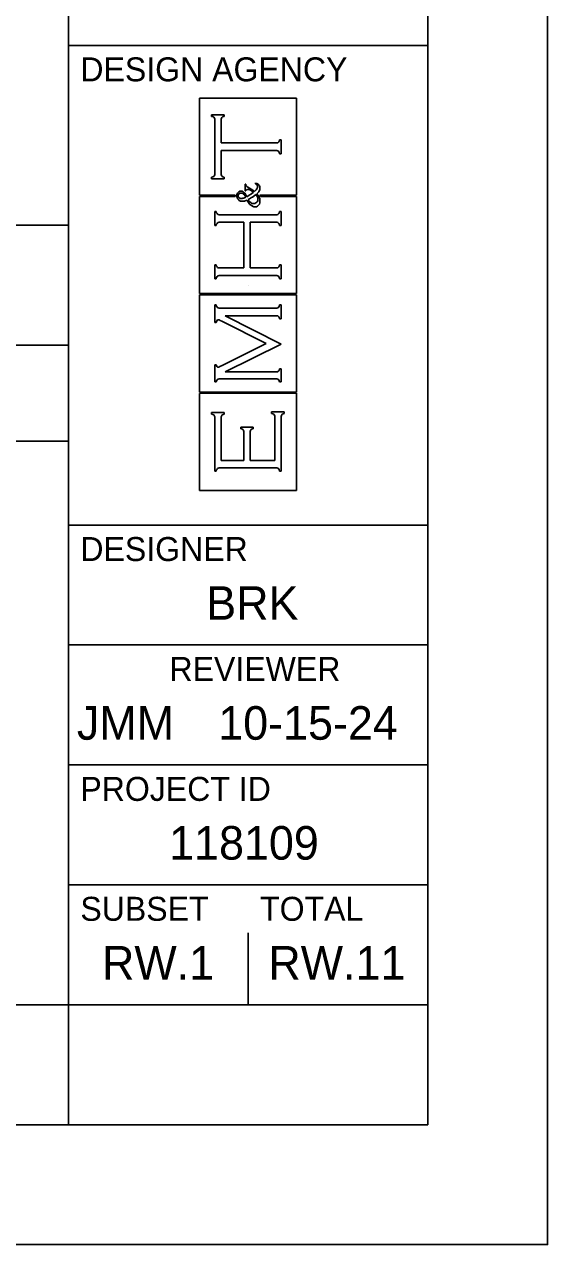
# Model space of a CAD drawing. Extents: x 0 to 34, y -5.4 to 22.
# Drawn here: x 31.82 to 34, y 0 to 5.09 of the extents above; entities that cross this region are included whole.
import ezdxf

# ---------------------------------------------------------------- set-up
doc = ezdxf.new("R2010")
doc.units = 0
for name, color, linetype in [('SH_Border', 7, 'Continuous'), ('SH_Cut_Line', 7, 'Continuous'), ('SH_Data', 7, 'Continuous')]:
    doc.layers.add(name, color=color, linetype=linetype)

msp = doc.modelspace()

# ---------------------------------------------------------------- linework, layer by layer
at = {"layer": 'SH_Border'}
for p, q in [((32, 0.5), (32, 21.5)), ((32, 5), (33.5, 5)), ((32, 3), (33.5, 3)), ((32, 2.5), (33.5, 2.5)), ((32, 2), (33.5, 2)), ((32, 1.5), (33.5, 1.5)), ((32, 1), (33.5, 1))]:
    msp.add_line(p, q, dxfattribs=at)
msp.add_lwpolyline([(1.5, 21.5), (33.5, 21.5), (33.5, 0.5), (1.5, 0.5)], close=True, dxfattribs=at)
at = {"layer": 'SH_Cut_Line'}
msp.add_lwpolyline([(0, 0), (34, 0), (34, 22), (0, 22)], close=True, dxfattribs=at)
at = {"layer": 'SH_Data'}
for p, q in [((32, 3.75), (32, 7)), ((32.9517, 4.7794), (32.547, 4.7794)), ((32.547, 4.7794), (32.547, 4.3748)), ((32.9517, 4.3748), (32.9517, 4.7794)), ((32.5978, 4.7041), (32.5978, 4.7106)), ((32.5978, 4.7106), (32.6505, 4.7106)), ((32.603, 4.7029), (32.5978, 4.7041)), ((32.6064, 4.7011), (32.603, 4.7029)), ((32.6082, 4.6987), (32.6064, 4.7011)), ((32.6099, 4.6964), (32.6082, 4.6987)), ((32.6108, 4.6924), (32.6099, 4.6964)), ((32.6108, 4.6867), (32.6108, 4.6924)), ((32.6108, 4.4675), (32.6108, 4.6867)), ((32.6383, 4.6964), (32.6375, 4.6924)), ((32.6375, 4.6924), (32.6375, 4.6867)), ((32.6375, 4.6867), (32.6375, 4.593)), ((32.64, 4.6987), (32.6383, 4.6964)), ((32.6418, 4.7011), (32.64, 4.6987)), ((32.6452, 4.7029), (32.6418, 4.7011)), ((32.6505, 4.7041), (32.6452, 4.7029)), ((32.6505, 4.7106), (32.6505, 4.7041)), ((32.6375, 4.593), (32.8639, 4.593)), ((32.8639, 4.593), (32.8695, 4.593)), ((32.8695, 4.593), (32.8734, 4.5939)), ((32.8734, 4.5939), (32.8758, 4.5956)), ((32.8758, 4.5956), (32.8782, 4.5974)), ((32.8782, 4.5974), (32.88, 4.6008)), ((32.88, 4.6008), (32.8814, 4.606)), ((32.8814, 4.606), (32.8879, 4.606)), ((32.8879, 4.606), (32.8879, 4.5483)), ((32.8639, 4.5612), (32.6375, 4.5612)), ((32.6375, 4.5612), (32.6375, 4.4676)), ((32.8696, 4.5612), (32.8639, 4.5612)), ((32.8736, 4.5604), (32.8696, 4.5612)), ((32.8759, 4.5586), (32.8736, 4.5604)), ((32.8782, 4.5568), (32.8759, 4.5586)), ((32.88, 4.5534), (32.8782, 4.5568)), ((32.8814, 4.5483), (32.88, 4.5534)), ((32.8879, 4.5483), (32.8814, 4.5483)), ((32.5978, 4.4501), (32.603, 4.4513)), ((32.5978, 4.4436), (32.5978, 4.4501)), ((32.6505, 4.4436), (32.5978, 4.4436)), ((32.603, 4.4513), (32.6064, 4.4531)), ((32.6064, 4.4531), (32.6082, 4.4555)), ((32.6082, 4.4555), (32.6099, 4.4579)), ((32.6099, 4.4579), (32.6108, 4.4619)), ((32.6108, 4.4619), (32.6108, 4.4675)), ((32.6375, 4.4676), (32.6375, 4.4619)), ((32.6375, 4.4619), (32.6383, 4.4579)), ((32.6383, 4.4579), (32.6401, 4.4555)), ((32.6401, 4.4555), (32.6418, 4.4531)), ((32.6418, 4.4531), (32.6452, 4.4513)), ((32.6452, 4.4513), (32.6505, 4.4501)), ((32.6505, 4.4501), (32.6505, 4.4436)), ((32.7035, 4.3788), (32.7051, 4.3832)), ((32.7035, 4.3734), (32.7035, 4.3788)), ((32.7051, 4.3832), (32.7082, 4.3866)), ((32.7082, 4.3866), (32.7114, 4.39)), ((32.7094, 4.3787), (32.7083, 4.3762)), ((32.7083, 4.3762), (32.7083, 4.3732)), ((32.7115, 4.3807), (32.7094, 4.3787)), ((32.7114, 4.39), (32.7153, 4.3917)), ((32.7137, 4.3827), (32.7115, 4.3807)), ((32.7164, 4.3837), (32.7137, 4.3827)), ((32.7153, 4.3917), (32.7199, 4.3917)), ((32.7196, 4.3837), (32.7164, 4.3837)), ((32.7238, 4.3837), (32.7196, 4.3837)), ((32.7199, 4.3917), (32.7247, 4.3917)), ((32.7276, 4.3823), (32.7238, 4.3837)), ((32.7247, 4.3917), (32.7289, 4.39)), ((32.731, 4.3795), (32.7276, 4.3823)), ((32.7289, 4.39), (32.7325, 4.3867)), ((32.7344, 4.3767), (32.731, 4.3795)), ((32.7325, 4.3867), (32.7361, 4.3834)), ((32.7374, 4.3725), (32.7344, 4.3767)), ((32.7361, 4.3834), (32.74, 4.3775)), ((32.7383, 4.3931), (32.7383, 4.4216)), ((32.7383, 4.4216), (32.7408, 4.4216)), ((32.7408, 4.3931), (32.7383, 4.3931)), ((32.74, 4.3775), (32.7443, 4.3691)), ((32.7408, 4.4216), (32.7411, 4.4177)), ((32.741, 4.395), (32.7408, 4.3931)), ((32.7418, 4.3964), (32.741, 4.395)), ((32.7411, 4.4177), (32.742, 4.4148)), ((32.743, 4.3974), (32.7418, 4.3964)), ((32.742, 4.4148), (32.7434, 4.4129)), ((32.7446, 4.3987), (32.743, 4.3974)), ((32.7434, 4.4129), (32.7448, 4.411)), ((32.7464, 4.3994), (32.7446, 4.3987)), ((32.7448, 4.411), (32.7491, 4.4081)), ((32.7485, 4.3994), (32.7464, 4.3994)), ((32.7549, 4.3994), (32.7485, 4.3994)), ((32.7491, 4.4081), (32.7562, 4.4041)), ((32.7545, 4.3751), (32.7638, 4.3812)), ((32.7629, 4.3954), (32.7549, 4.3994)), ((32.7562, 4.4041), (32.7634, 4.4001)), ((32.7723, 4.3874), (32.7629, 4.3954)), ((32.7634, 4.4001), (32.77, 4.3956)), ((32.7638, 4.3812), (32.7723, 4.3874)), ((32.77, 4.3956), (32.7762, 4.3905)), ((32.7821, 4.3776), (32.7741, 4.3716)), ((32.7762, 4.3905), (32.7809, 4.3945)), ((32.7788, 4.4232), (32.7806, 4.4258)), ((32.7821, 4.4224), (32.7788, 4.4232)), ((32.7806, 4.4258), (32.787, 4.4241)), ((32.7809, 4.3945), (32.7841, 4.3981)), ((32.7846, 4.4208), (32.7821, 4.4224)), ((32.7859, 4.373), (32.7821, 4.3776)), ((32.7841, 4.3981), (32.786, 4.4013)), ((32.7863, 4.4187), (32.7846, 4.4208)), ((32.786, 4.4013), (32.7879, 4.4044)), ((32.7909, 4.3856), (32.786, 4.3811)), ((32.786, 4.3811), (32.7911, 4.3755)), ((32.7879, 4.4165), (32.7863, 4.4187)), ((32.787, 4.4241), (32.7917, 4.4214)), ((32.7888, 4.4139), (32.7879, 4.4165)), ((32.7879, 4.4044), (32.7888, 4.4076)), ((32.7888, 4.4108), (32.7888, 4.4139)), ((32.7888, 4.4076), (32.7888, 4.4108)), ((32.7943, 4.3898), (32.7909, 4.3856)), ((32.7911, 4.3755), (32.7946, 4.3705)), ((32.7917, 4.4214), (32.7948, 4.4177)), ((32.7964, 4.3936), (32.7943, 4.3898)), ((32.7948, 4.4177), (32.7979, 4.414)), ((32.7984, 4.3974), (32.7964, 4.3936)), ((32.7979, 4.414), (32.7994, 4.4097)), ((32.7994, 4.4011), (32.7984, 4.3974)), ((32.7994, 4.4097), (32.7994, 4.4048)), ((32.7994, 4.4048), (32.7994, 4.4011)), ((32.547, 4.3748), (32.6961, 4.3748)), ((32.6956, 4.3694), (32.5471, 4.3694)), ((32.5471, 4.3694), (32.5471, 3.9648)), ((32.6961, 4.3748), (32.6956, 4.3694)), ((32.7035, 4.3678), (32.7035, 4.3734)), ((32.705, 4.3628), (32.7035, 4.3678)), ((32.7082, 4.3583), (32.705, 4.3628)), ((32.7123, 4.3526), (32.7082, 4.3583)), ((32.7083, 4.3732), (32.7083, 4.3693)), ((32.7083, 4.3693), (32.7097, 4.3664)), ((32.7097, 4.3664), (32.7125, 4.3644)), ((32.7182, 4.3498), (32.7123, 4.3526)), ((32.7125, 4.3644), (32.7152, 4.3623)), ((32.7152, 4.3623), (32.7179, 4.3614)), ((32.7179, 4.3614), (32.7205, 4.3614)), ((32.7259, 4.3498), (32.7182, 4.3498)), ((32.7205, 4.3614), (32.7227, 4.3614)), ((32.7227, 4.3614), (32.7252, 4.3617)), ((32.7252, 4.3617), (32.7279, 4.3625)), ((32.7286, 4.3498), (32.7259, 4.3498)), ((32.7279, 4.3625), (32.7307, 4.3632)), ((32.7315, 4.3502), (32.7286, 4.3498)), ((32.7307, 4.3632), (32.7347, 4.3647)), ((32.7345, 4.3509), (32.7315, 4.3502)), ((32.7375, 4.3517), (32.7345, 4.3509)), ((32.7347, 4.3647), (32.7401, 4.3668)), ((32.7401, 4.3668), (32.7374, 4.3725)), ((32.7413, 4.3531), (32.7375, 4.3517)), ((32.746, 4.3552), (32.7413, 4.3531)), ((32.7443, 4.3691), (32.7545, 4.3751)), ((32.7519, 4.3444), (32.746, 4.3552)), ((32.7561, 4.3603), (32.7505, 4.3575)), ((32.7505, 4.3575), (32.7537, 4.3521)), ((32.7575, 4.337), (32.7519, 4.3444)), ((32.7537, 4.3521), (32.7571, 4.3481)), ((32.7607, 4.3628), (32.7561, 4.3603)), ((32.7571, 4.3481), (32.7609, 4.3454)), ((32.7629, 4.3331), (32.7575, 4.337)), ((32.7644, 4.3651), (32.7607, 4.3628)), ((32.7609, 4.3454), (32.7646, 4.3427)), ((32.7684, 4.3292), (32.7629, 4.3331)), ((32.7681, 4.3674), (32.7644, 4.3651)), ((32.7646, 4.3427), (32.7687, 4.3413)), ((32.7741, 4.3716), (32.7681, 4.3674)), ((32.7738, 4.3273), (32.7684, 4.3292)), ((32.7687, 4.3413), (32.7731, 4.3413)), ((32.7731, 4.3413), (32.7779, 4.3413)), ((32.7793, 4.3273), (32.7738, 4.3273)), ((32.7779, 4.3413), (32.7822, 4.3429)), ((32.7848, 4.3273), (32.7793, 4.3273)), ((32.7822, 4.3429), (32.7858, 4.346)), ((32.7895, 4.3294), (32.7848, 4.3273)), ((32.7858, 4.346), (32.7895, 4.3491)), ((32.7884, 4.3694), (32.7859, 4.373)), ((32.7896, 4.3668), (32.7884, 4.3694)), ((32.7895, 4.3491), (32.7913, 4.3533)), ((32.7935, 4.3338), (32.7895, 4.3294)), ((32.7907, 4.3642), (32.7896, 4.3668)), ((32.7913, 4.3614), (32.7907, 4.3642)), ((32.7913, 4.3586), (32.7913, 4.3614)), ((32.7913, 4.3533), (32.7913, 4.3586)), ((32.7975, 4.3382), (32.7935, 4.3338)), ((32.7946, 4.3705), (32.7965, 4.366)), ((32.7965, 4.366), (32.7985, 4.3615)), ((32.7994, 4.3441), (32.7975, 4.3382)), ((32.7985, 4.3615), (32.7994, 4.3567)), ((32.8029, 4.3694), (32.799, 4.3748)), ((32.799, 4.3748), (32.9517, 4.3748)), ((32.7994, 4.3567), (32.7994, 4.3516)), ((32.7994, 4.3516), (32.7994, 4.3441)), ((32.9517, 4.3694), (32.8029, 4.3694)), ((32.9517, 3.9648), (32.9517, 4.3694)), ((32.6108, 4.2493), (32.6108, 4.3071)), ((32.6108, 4.3071), (32.6173, 4.3071)), ((32.6173, 4.3071), (32.6186, 4.3019)), ((32.6186, 4.3019), (32.6205, 4.2985)), ((32.6205, 4.2985), (32.6228, 4.2967)), ((32.6228, 4.2967), (32.6251, 4.2949)), ((32.6251, 4.2949), (32.629, 4.2941)), ((32.629, 4.2941), (32.6347, 4.2941)), ((32.6347, 4.2941), (32.8639, 4.2941)), ((32.8639, 4.2941), (32.8695, 4.2941)), ((32.8695, 4.2941), (32.8734, 4.2949)), ((32.8734, 4.2949), (32.8758, 4.2967)), ((32.8758, 4.2967), (32.8782, 4.2985)), ((32.8782, 4.2985), (32.88, 4.3019)), ((32.88, 4.3019), (32.8814, 4.3071)), ((32.8814, 4.3071), (32.8879, 4.3071)), ((32.8879, 4.3071), (32.8879, 4.2493)), ((32.6173, 4.2493), (32.6108, 4.2493)), ((32.6185, 4.2545), (32.6173, 4.2493)), ((32.6203, 4.2579), (32.6185, 4.2545)), ((32.6227, 4.2597), (32.6203, 4.2579)), ((32.625, 4.2614), (32.6227, 4.2597)), ((32.629, 4.2623), (32.625, 4.2614)), ((32.6347, 4.2623), (32.629, 4.2623)), ((32.732, 4.2623), (32.6347, 4.2623)), ((32.732, 4.0718), (32.732, 4.2623)), ((32.8639, 4.2623), (32.7587, 4.2623)), ((32.7587, 4.2623), (32.7587, 4.0718)), ((32.8696, 4.2623), (32.8639, 4.2623)), ((32.8736, 4.2614), (32.8696, 4.2623)), ((32.8759, 4.2597), (32.8736, 4.2614)), ((32.8782, 4.2579), (32.8759, 4.2597)), ((32.88, 4.2545), (32.8782, 4.2579)), ((32.8814, 4.2493), (32.88, 4.2545)), ((32.8879, 4.2493), (32.8814, 4.2493)), ((32.6108, 4.0271), (32.6108, 4.0848)), ((32.6108, 4.0848), (32.6173, 4.0848)), ((32.6173, 4.0848), (32.6186, 4.0797)), ((32.6186, 4.0797), (32.6205, 4.0762)), ((32.6205, 4.0762), (32.6228, 4.0745)), ((32.6228, 4.0745), (32.6251, 4.0727)), ((32.6251, 4.0727), (32.629, 4.0718)), ((32.629, 4.0718), (32.6347, 4.0718)), ((32.6347, 4.0718), (32.732, 4.0718)), ((32.7587, 4.0718), (32.8639, 4.0718)), ((32.8639, 4.0718), (32.8696, 4.0718)), ((32.8696, 4.0718), (32.8736, 4.0727)), ((32.8736, 4.0727), (32.8759, 4.0744)), ((32.8759, 4.0744), (32.8782, 4.076)), ((32.8782, 4.076), (32.88, 4.0795)), ((32.88, 4.0795), (32.8814, 4.0848)), ((32.8814, 4.0848), (32.8879, 4.0848)), ((32.8879, 4.0848), (32.8879, 4.0271)), ((32.6173, 4.0271), (32.6108, 4.0271)), ((32.6185, 4.0322), (32.6173, 4.0271)), ((32.6203, 4.0357), (32.6185, 4.0322)), ((32.6227, 4.0374), (32.6203, 4.0357)), ((32.625, 4.0392), (32.6227, 4.0374)), ((32.6291, 4.0401), (32.625, 4.0392)), ((32.6347, 4.0401), (32.6291, 4.0401)), ((32.8639, 4.0401), (32.6347, 4.0401)), ((32.8696, 4.0401), (32.8639, 4.0401)), ((32.8736, 4.0392), (32.8696, 4.0401)), ((32.8759, 4.0375), (32.8736, 4.0392)), ((32.8782, 4.0358), (32.8759, 4.0375)), ((32.88, 4.0324), (32.8782, 4.0358)), ((32.8814, 4.0271), (32.88, 4.0324)), ((32.8879, 4.0271), (32.8814, 4.0271)), ((32.75, 4), (32.75, 4)), ((32.9516, 3.9593), (32.547, 3.9593)), ((32.547, 3.9593), (32.547, 3.5547)), ((32.5471, 3.9648), (32.9517, 3.9648)), ((32.6108, 3.8452), (32.6108, 3.9176)), ((32.6108, 3.9176), (32.6173, 3.9176)), ((32.6173, 3.9176), (32.6186, 3.9124)), ((32.88, 3.9124), (32.8814, 3.9176)), ((32.8814, 3.9176), (32.8879, 3.9176)), ((32.8879, 3.9176), (32.8879, 3.8598)), ((32.9517, 3.5547), (32.9516, 3.9593)), ((32.6186, 3.9124), (32.6205, 3.909)), ((32.6205, 3.909), (32.6228, 3.9072)), ((32.6228, 3.9072), (32.6251, 3.9055)), ((32.6251, 3.9055), (32.6291, 3.9046)), ((32.6291, 3.9046), (32.6347, 3.9046)), ((32.6347, 3.9046), (32.8639, 3.9046)), ((32.8639, 3.8728), (32.6543, 3.8728)), ((32.6543, 3.8728), (32.8879, 3.7548)), ((32.8639, 3.9046), (32.8695, 3.9046)), ((32.8696, 3.8728), (32.8639, 3.8728)), ((32.8695, 3.9046), (32.8734, 3.9055)), ((32.8736, 3.872), (32.8696, 3.8728)), ((32.8734, 3.9055), (32.8758, 3.9072)), ((32.8759, 3.8703), (32.8736, 3.872)), ((32.8758, 3.9072), (32.8782, 3.909)), ((32.8782, 3.8686), (32.8759, 3.8703)), ((32.8782, 3.909), (32.88, 3.9124)), ((32.88, 3.8651), (32.8782, 3.8686)), ((32.6173, 3.8452), (32.6108, 3.8452)), ((32.6196, 3.8518), (32.6173, 3.8452)), ((32.6225, 3.8551), (32.6196, 3.8518)), ((32.626, 3.8551), (32.6225, 3.8551)), ((32.6287, 3.8551), (32.626, 3.8551)), ((32.6333, 3.8535), (32.6287, 3.8551)), ((32.6398, 3.8502), (32.6333, 3.8535)), ((32.8253, 3.7574), (32.6398, 3.8502)), ((32.8814, 3.8598), (32.88, 3.8651)), ((32.8879, 3.8598), (32.8814, 3.8598)), ((32, 3.75), (29.2, 3.75)), ((32, 3.75), (29.2, 3.75)), ((32, 0.5), (32, 3.75)), ((32, 0.5), (32, 3.75)), ((32.6414, 3.665), (32.8253, 3.7574)), ((32.8879, 3.7548), (32.6543, 3.6383)), ((32.6108, 3.5965), (32.6108, 3.6682)), ((32.6108, 3.6682), (32.6173, 3.6682)), ((32.6173, 3.6682), (32.6196, 3.6616)), ((32.6326, 3.6605), (32.6414, 3.665)), ((32.6196, 3.6616), (32.6224, 3.6583)), ((32.6224, 3.6583), (32.6258, 3.6583)), ((32.6258, 3.6583), (32.6274, 3.6583)), ((32.6274, 3.6583), (32.6326, 3.6605)), ((32.6543, 3.6383), (32.8639, 3.6383)), ((32.8639, 3.6383), (32.8694, 3.6383)), ((32.8694, 3.6383), (32.8734, 3.6392)), ((32.8734, 3.6392), (32.8758, 3.641)), ((32.8758, 3.641), (32.8782, 3.6427)), ((32.8782, 3.6427), (32.88, 3.6462)), ((32.88, 3.6462), (32.8814, 3.6513)), ((32.8814, 3.6513), (32.8879, 3.6513)), ((32.8879, 3.6513), (32.8879, 3.5965)), ((32.6173, 3.5965), (32.6108, 3.5965)), ((32.6185, 3.6016), (32.6173, 3.5965)), ((32.6203, 3.605), (32.6185, 3.6016)), ((32.6227, 3.6068), (32.6203, 3.605)), ((32.625, 3.6086), (32.6227, 3.6068)), ((32.6291, 3.6094), (32.625, 3.6086)), ((32.6347, 3.6094), (32.6291, 3.6094)), ((32.8639, 3.6095), (32.6347, 3.6094)), ((32.8696, 3.6095), (32.8639, 3.6095)), ((32.8736, 3.6086), (32.8696, 3.6095)), ((32.8759, 3.6068), (32.8736, 3.6086)), ((32.8782, 3.6051), (32.8759, 3.6068)), ((32.88, 3.6016), (32.8782, 3.6051)), ((32.8814, 3.5965), (32.88, 3.6016)), ((32.8879, 3.5965), (32.8814, 3.5965)), ((32.547, 3.5547), (32.9517, 3.5547)), ((32.9517, 3.5493), (32.547, 3.5492)), ((32.547, 3.5492), (32.547, 3.1447)), ((32.9517, 3.1447), (32.9517, 3.5493)), ((32.5978, 3.4624), (32.5978, 3.4689)), ((32.5978, 3.4689), (32.6505, 3.4689)), ((32.603, 3.4611), (32.5978, 3.4624)), ((32.6065, 3.4592), (32.603, 3.4611)), ((32.6454, 3.4612), (32.642, 3.4594)), ((32.6505, 3.4624), (32.6454, 3.4612)), ((32.6505, 3.4689), (32.6505, 3.4624)), ((32.8482, 3.4653), (32.8482, 3.4718)), ((32.8482, 3.4718), (32.9009, 3.4718)), ((32.8533, 3.4641), (32.8482, 3.4653)), ((32.8568, 3.4623), (32.8533, 3.4641)), ((32.8586, 3.4599), (32.8568, 3.4623)), ((32.8603, 3.4575), (32.8586, 3.4599)), ((32.8905, 3.4597), (32.8888, 3.4573)), ((32.8923, 3.4621), (32.8905, 3.4597)), ((32.8957, 3.4639), (32.8923, 3.4621)), ((32.9009, 3.4653), (32.8957, 3.4639)), ((32.9009, 3.4718), (32.9009, 3.4653)), ((32.6082, 3.4569), (32.6065, 3.4592)), ((32.61, 3.4546), (32.6082, 3.4569)), ((32.6108, 3.4506), (32.61, 3.4546)), ((32.6108, 3.4449), (32.6108, 3.4506)), ((32.6108, 3.225), (32.6108, 3.4449)), ((32.6384, 3.4546), (32.6375, 3.4506)), ((32.6375, 3.4506), (32.6375, 3.4449)), ((32.6375, 3.4449), (32.6375, 3.2697)), ((32.6402, 3.457), (32.6384, 3.4546)), ((32.642, 3.4594), (32.6402, 3.457)), ((32.8612, 3.4535), (32.8603, 3.4575)), ((32.8612, 3.4478), (32.8612, 3.4535)), ((32.8612, 3.2697), (32.8612, 3.4478)), ((32.8888, 3.4573), (32.8879, 3.4533)), ((32.8879, 3.4533), (32.8879, 3.4476)), ((32.8879, 3.4476), (32.8879, 3.225)), ((32.719, 3.4018), (32.719, 3.4083)), ((32.719, 3.4083), (32.7717, 3.4083)), ((32.7242, 3.4006), (32.719, 3.4018)), ((32.7276, 3.3988), (32.7242, 3.4006)), ((32.7294, 3.3964), (32.7276, 3.3988)), ((32.7312, 3.394), (32.7294, 3.3964)), ((32.732, 3.39), (32.7312, 3.394)), ((32.732, 3.3844), (32.732, 3.39)), ((32.732, 3.2697), (32.732, 3.3844)), ((32.7596, 3.394), (32.7587, 3.39)), ((32.7587, 3.39), (32.7587, 3.3844)), ((32.7587, 3.3844), (32.7587, 3.2697)), ((32.7614, 3.3964), (32.7596, 3.394)), ((32.7631, 3.3988), (32.7614, 3.3964)), ((32.7666, 3.4006), (32.7631, 3.3988)), ((32.7717, 3.4018), (32.7666, 3.4006)), ((32.7717, 3.4083), (32.7717, 3.4018)), ((32, 3.35), (29.2, 3.35)), ((32.6375, 3.2697), (32.732, 3.2697)), ((32.7587, 3.2697), (32.8612, 3.2697)), ((32.6173, 3.225), (32.6108, 3.225)), ((32.6187, 3.2301), (32.6173, 3.225)), ((32.6205, 3.2336), (32.6187, 3.2301)), ((32.6228, 3.2354), (32.6205, 3.2336)), ((32.6251, 3.2371), (32.6228, 3.2354)), ((32.6291, 3.238), (32.6251, 3.2371)), ((32.6348, 3.238), (32.6291, 3.238)), ((32.864, 3.238), (32.6348, 3.238)), ((32.8696, 3.238), (32.864, 3.238)), ((32.8736, 3.2372), (32.8696, 3.238)), ((32.8759, 3.2355), (32.8736, 3.2372)), ((32.8782, 3.2338), (32.8759, 3.2355)), ((32.88, 3.2303), (32.8782, 3.2338)), ((32.8814, 3.225), (32.88, 3.2303)), ((32.8879, 3.225), (32.8814, 3.225)), ((32.547, 3.1447), (32.9517, 3.1447)), ((32.75, 1), (32.75, 1.3)), ((32, 0.5), (29.2, 0.5)), ((32, 0.5), (29.2, 0.5))]:
    msp.add_line(p, q, dxfattribs=at)
for points in [[(32, 3.75), (32, 4.25), (29.2, 4.25), (29.2, 3.75)], [(32, 0.5), (32, 1), (29.2, 1), (29.2, 0.5)]]:
    msp.add_lwpolyline(points, close=True, dxfattribs=at)

# ---------------------------------------------------------------- texts
for s, height, p in [('DESIGN AGENCY', 0.1, (32.05, 4.85)), ('DESIGNER', 0.1, (32.05, 2.85)), ('BRK', 0.14, (32.5754, 2.605)), ('REVIEWER', 0.1, (32.4218, 2.35)), ('JMM', 0.14, (32.0355, 2.105)), ('10-15-24', 0.14, (32.6254, 2.105)), ('PROJECT ID', 0.1, (32.05, 1.85)), ('118109', 0.14, (32.4204, 1.605)), ('SUBSET', 0.1, (32.05, 1.35)), ('TOTAL', 0.1, (32.8, 1.35)), ('RW.1', 0.14, (32.1402, 1.105)), ('RW.11', 0.14, (32.8344, 1.105))]:
    msp.add_text(s, height=height, dxfattribs=at).set_placement(p)

doc.saveas('drawing.dxf')
